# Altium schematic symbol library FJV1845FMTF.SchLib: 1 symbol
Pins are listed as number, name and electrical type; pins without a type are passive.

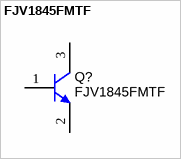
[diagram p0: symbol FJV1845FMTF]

## FJV1845FMTF
designator Q?
Transistor, NPN, 140 V, 0.6 A, SOT-23; Manufacturer: ON Semiconductor; CompType: BJT; PNP: 0; NPN: 1; Vceo_V: 120; Vcesat1_V: 0.25; Value: 120 V; IcRated_A: 0.6; Value1: 0.6 A; HfeMax: 250; TaMin_C: -55; TaMax_C: 150; U/M: EA
footprint SOT-23
footprint SOT-23M
footprint SOT-23L
pins: 1 B, 2 E, 3 C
